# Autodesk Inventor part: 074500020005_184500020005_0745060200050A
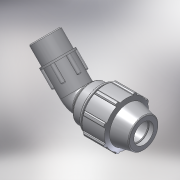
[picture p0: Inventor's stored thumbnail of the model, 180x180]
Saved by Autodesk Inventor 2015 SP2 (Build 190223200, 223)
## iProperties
Created: 2017-02
Part Number: 074500020005_184500020005_0745060200050A
Material: PVC-Piping
Description: PLASSON 45° ELBOW MALE ADAPTOR 20-1/2"
Document SubType Name: Modeling
Designer: KIM
Mass: 92.6774 g
Surface Area: 199.44 cm^2
Volume: 66.1981 cm^3
Density: 1.4 g/cm^3
Appearance: Smooth - White
Author: KIM
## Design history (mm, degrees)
derived "07450.ipt"
feature "Solid1::07450.ipt"
tag "TaggingFeature1"
body "Solid1"
other parameters: "d4" = 5.33333, "d5" = 16, "d7" = 48, "d9" = 9.14286, "d11" = 2.13333, "d13" = 120 deg, "d15" = 12 deg, "d16" = 41.76, "d18" = 1, "d19" = 35 deg, "d20" = 17.5 deg, "d21" = 44.64, "d23" = 0, "d25" = 360 deg, "d27" = 0.96, "d33" = 0.4, "d42" = 23.68, "d43" = 1.44, "d46" = 0.6, "d51" = 64, "d68" = 2.13333, "d73" = 20.955, "d74" = 17, "d75" = 24.09825, "d76" = 14.6685, "d77" = 18.7, "d80" = 0.62865, "d83" = 0, "d84" = 0, "d91" = 36, "d93" = 57, "d94" = 20.955, "d95" = 14.6685, "d96" = 9.38667, "d97" = 50 deg, "d98" = 135 deg, "d99" = 1.5, "d100" = 10.4775, "d101" = 1, "d102" = 17, "d103" = 0, "d104" = 0.68, "d106" = 360 deg, "E_" = 48, "A_" = 64, "l_" = 57, "l_2" = 17, "R_" = 20.955
